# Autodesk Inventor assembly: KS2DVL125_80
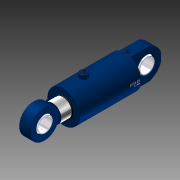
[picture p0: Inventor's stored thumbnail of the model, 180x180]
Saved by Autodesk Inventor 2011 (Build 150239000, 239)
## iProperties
Created: 2010-11
Document SubType Name: Assembly
Designer: TB
Mass: 566.294 g
Surface Area: 1153.75 cm^2
Volume: 566.294 cm^3
Density: 1 g/cm^3
Description: KS2DVL 125/80 - 100 mm
Slaglengde: 100,000 mm
Author: TB
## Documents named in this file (6)
- C:\Vault\Sylinderteknikk\Projects_ST\3D.nettkatalog\KS2-Series\KS2DVL\KS2DVL125_80\KS2DVL125_80.iam
- C:\Vault\Sylinderteknikk\Projects_ST\3D.nettkatalog\KS2-Series\KS2DVL\KS2DVL125_80\KS2DVL125_80_stang.ipt
- C:\Vault\Sylinderteknikk\Projects_ST\3D.nettkatalog\KS2-Series\KS2DVL\KS2DVL125_80\KS2DVL125_80_Parameters.ipt
- C:\Vault\Sylinderteknikk\Projects_ST\3D.nettkatalog\KS2-Series\KS2DVL\KS2DVL125_80\KS2DVL125_80_body..ipt
- C:\Vault\Sylinderteknikk\Projects_ST\Øyer\Klinkby.KS.Øyer\KS.60.eye.komplett\KS.60.eye.komplett.ipt
- C:\Vault\Sylinderteknikk\Projects_ST\Øyer\Klinkby.KS.Øyer\KS.60.eye.komplett\Kule60HO.ipt
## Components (5 placed, 5 different names)
1. KS2DVL125_80_Parameters:3
2. KS2DVL125_80_stang:1 — Mate:1, FriMate:2, Mate:3, Insert:1
3. KS2DVL125_80_body.:1 — Mate:1, FriMate:2, Mate:3, Angle:1, Insert:2
4. KS.60.eye.komplett:1 — Insert:1, Angle:1
5. Kule60HO:1 — Insert:2
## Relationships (6: Mate 3, Insert 2, Angle 1)
- Mate:1: KS2DVL125_80_stang:1 ↔ KS2DVL125_80_body.:1
- FriMate:2 [Mate]: KS2DVL125_80_stang:1 ↔ KS2DVL125_80_body.:1
- Mate:3: KS2DVL125_80_stang:1 ↔ KS2DVL125_80_body.:1
- Insert:1: KS2DVL125_80_stang:1 ↔ KS.60.eye.komplett:1
- Angle:1: KS2DVL125_80_body.:1 ↔ KS.60.eye.komplett:1
- Insert:2: KS2DVL125_80_body.:1 ↔ Kule60HO:1
## Named parameters: Forlengelse_rør = 0, Vinkel_Minusport = 0
